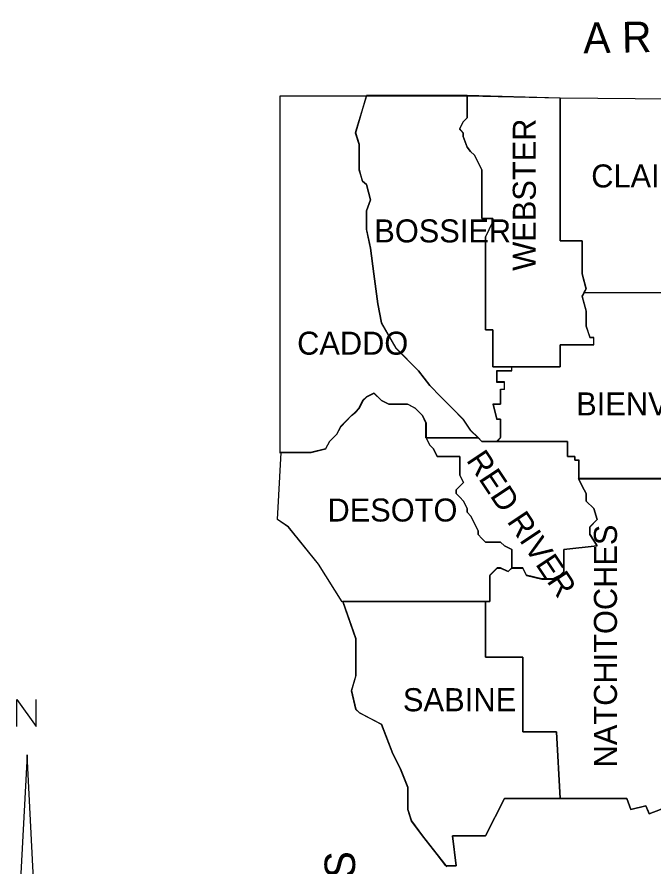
# Model space of a CAD drawing. Extents: x 0.19 to 2.82, y 0.04 to 1.79.
# Drawn here: x 2.1624 to 2.2917, y 1.594 to 1.7666 of the extents above; entities that cross this region are included whole.
import ezdxf

# ---------------------------------------------------------------- set-up
doc = ezdxf.new("R2010")
doc.units = 0
for name, color, linetype in [('Dist04', 7, 'Continuous'), ('Dist08', 7, 'Continuous'), ('Standard Info', 7, 'Continuous')]:
    doc.layers.add(name, color=color, linetype=linetype)

msp = doc.modelspace()

# ---------------------------------------------------------------- linework, layer by layer
at = {"layer": 'Dist04'}
for p, q in [((2.2159, 1.678), (2.2159, 1.75058)), ((2.2159, 1.75058), (2.23332, 1.75058)), ((2.2334, 1.75067), (2.2539, 1.75067)), ((2.2539, 1.75067), (2.27282, 1.75017)), ((2.27282, 1.75017), (2.3099, 1.74983)), ((2.21532, 1.66442), (2.21607, 1.678)), ((2.21607, 1.678), (2.2159, 1.678))]:
    msp.add_line(p, q, dxfattribs=at)
for points in [[(2.27657, 1.67275), (2.27732, 1.67117), (2.27807, 1.66967), (2.27807, 1.66817), (2.27965, 1.66667), (2.28032, 1.66442), (2.27882, 1.66292), (2.27882, 1.66142), (2.28032, 1.65908), (2.27357, 1.65833), (2.27357, 1.65383), (2.27282, 1.65308), (2.27132, 1.65233), (2.26907, 1.65233), (2.26599, 1.65308), (2.26524, 1.65458), (2.26299, 1.65458)], [(2.30307, 1.67275), (2.27665, 1.67275)], [(2.22849, 1.64767), (2.22365, 1.65533), (2.21757, 1.66292), (2.21532, 1.66442)], [(2.26299, 1.65458), (2.26224, 1.65383), (2.26065, 1.65458), (2.25999, 1.65458), (2.25849, 1.65308), (2.25849, 1.64775), (2.25765, 1.64775)], [(2.25765, 1.64775), (2.22865, 1.64775)]]:
    msp.add_lwpolyline(points, dxfattribs=at)
at = {"layer": 'Dist08'}
for points in [[(2.27657, 1.67275), (2.27732, 1.67117), (2.27807, 1.66967), (2.27807, 1.66817), (2.27965, 1.66667), (2.28032, 1.66442), (2.27882, 1.66292), (2.27882, 1.66142), (2.28032, 1.65908), (2.27357, 1.65833), (2.27357, 1.65383), (2.27282, 1.65308), (2.27132, 1.65233), (2.26907, 1.65233), (2.26599, 1.65308), (2.26524, 1.65458), (2.26299, 1.65458)], [(2.30307, 1.67275), (2.27665, 1.67275)], [(2.26299, 1.65458), (2.26224, 1.65383), (2.26065, 1.65458), (2.25999, 1.65458), (2.25849, 1.65308), (2.25849, 1.64775), (2.25765, 1.64775)], [(2.22865, 1.64775), (2.23124, 1.64025), (2.23124, 1.63267), (2.2304, 1.62967), (2.23124, 1.62583), (2.23199, 1.62508), (2.23649, 1.62283), (2.23882, 1.61675), (2.24032, 1.61375), (2.24182, 1.61), (2.24182, 1.60542), (2.24257, 1.60317), (2.24482, 1.60008), (2.24782, 1.59633), (2.24957, 1.59408)], [(2.25765, 1.64775), (2.22865, 1.64775)]]:
    msp.add_lwpolyline(points, dxfattribs=at)
at = {"layer": 'Standard Info'}
for p, q in [((2.2159, 1.67792), (2.2159, 1.75058)), ((2.2159, 1.75058), (2.23332, 1.75058)), ((2.23332, 1.75058), (2.2334, 1.75058)), ((2.2334, 1.75058), (2.2539, 1.75058)), ((2.2539, 1.75058), (2.27282, 1.75017)), ((2.27282, 1.75017), (2.3099, 1.74983)), ((2.27732, 1.70983), (2.27774, 1.71058)), ((2.2629, 1.69542), (2.25915, 1.69542)), ((2.24557, 1.681), (2.25615, 1.681)), ((2.2569, 1.68025), (2.25615, 1.68108)), ((2.2599, 1.68025), (2.2569, 1.68025)), ((2.21532, 1.66442), (2.21607, 1.678)), ((2.22865, 1.64775), (2.22849, 1.64767)), ((2.1644, 1.61657), (2.1624, 1.57857)), ((2.1664, 1.57857), (2.1644, 1.61657)), ((2.2909, 1.60458), (2.29249, 1.60517)), ((2.2499, 1.594), (2.24957, 1.594)), ((2.24965, 1.59383), (2.2499, 1.594))]:
    msp.add_line(p, q, dxfattribs=at)
for points in [[(2.2334, 1.75058), (2.23115, 1.743), (2.2319, 1.74075), (2.2319, 1.73775), (2.2319, 1.7355), (2.23265, 1.73317), (2.2334, 1.7325), (2.23424, 1.72942), (2.2334, 1.72717), (2.2334, 1.72333), (2.23424, 1.71958), (2.2349, 1.71433), (2.23574, 1.70825), (2.23649, 1.70442), (2.23949, 1.69917), (2.24399, 1.69467), (2.24632, 1.69167), (2.24857, 1.68933), (2.25082, 1.68708), (2.25307, 1.68475), (2.25457, 1.6825), (2.25615, 1.681), (2.24549, 1.681), (2.24549, 1.68175), (2.24549, 1.68408), (2.24482, 1.68558), (2.24332, 1.68708), (2.24174, 1.68783), (2.23949, 1.68783), (2.23799, 1.68783), (2.23649, 1.68858), (2.2349, 1.69008), (2.2349, 1.69008), (2.2334, 1.68933), (2.23265, 1.68858), (2.2319, 1.68708), (2.23115, 1.68625), (2.2304, 1.68558), (2.22815, 1.68333), (2.2274, 1.68175), (2.2259, 1.68025), (2.22507, 1.67875), (2.22207, 1.678), (2.21982, 1.678), (2.21607, 1.678)], [(2.25615, 1.68108), (2.25457, 1.68258), (2.25307, 1.68483), (2.25082, 1.68708), (2.24857, 1.68933), (2.24632, 1.69167), (2.24399, 1.69467), (2.23949, 1.69925), (2.23649, 1.70442), (2.23574, 1.70825), (2.2349, 1.71433), (2.23424, 1.71958), (2.2334, 1.72342), (2.2334, 1.72717), (2.23424, 1.72942), (2.2334, 1.7325), (2.23265, 1.73317), (2.23199, 1.7355), (2.23199, 1.73775), (2.23199, 1.74067), (2.23124, 1.743), (2.2334, 1.75058)], [(2.2539, 1.75058), (2.2539, 1.74608), (2.25307, 1.74525), (2.25232, 1.74375), (2.25307, 1.743), (2.25307, 1.74225), (2.2539, 1.74008), (2.25457, 1.73925), (2.2554, 1.7385), (2.25615, 1.73692), (2.2569, 1.7355), (2.2569, 1.73317), (2.2569, 1.73017), (2.2569, 1.72858), (2.2569, 1.72792), (2.2569, 1.72642), (2.2569, 1.72558), (2.25915, 1.72558), (2.25915, 1.72492), (2.25765, 1.72192), (2.25765, 1.703), (2.25915, 1.703), (2.25915, 1.69542), (2.2629, 1.69542), (2.2629, 1.69467), (2.2599, 1.69467), (2.2599, 1.69233), (2.2614, 1.69233), (2.2614, 1.69083), (2.26065, 1.69083), (2.26065, 1.68783), (2.25915, 1.68783), (2.2599, 1.68483), (2.26065, 1.68483), (2.26065, 1.68333), (2.26065, 1.68183), (2.26065, 1.68108), (2.2599, 1.68025)], [(2.25915, 1.69542), (2.25915, 1.703), (2.25765, 1.703), (2.25765, 1.72183), (2.25915, 1.72492), (2.25915, 1.72558), (2.2569, 1.72558), (2.2569, 1.72642), (2.2569, 1.72792), (2.2569, 1.72867), (2.2569, 1.73017), (2.2569, 1.73317), (2.2569, 1.7355), (2.25615, 1.737), (2.2554, 1.7385), (2.25457, 1.73925), (2.2539, 1.74008), (2.25307, 1.74225), (2.25307, 1.743), (2.2524, 1.74383), (2.25307, 1.74525), (2.2539, 1.74608), (2.2539, 1.75058)], [(2.27282, 1.75017), (2.27282, 1.72108), (2.27732, 1.72108), (2.27732, 1.7165), (2.27732, 1.71433), (2.27807, 1.71133), (2.27732, 1.70975), (2.27807, 1.70675), (2.27807, 1.70375), (2.27882, 1.70142), (2.27957, 1.70142), (2.27957, 1.69992), (2.27282, 1.69992), (2.27282, 1.69542), (2.2629, 1.69542)], [(2.27765, 1.7105), (2.27807, 1.71125), (2.27732, 1.71433), (2.27732, 1.7165), (2.27732, 1.72108), (2.27282, 1.72108), (2.27282, 1.75017)], [(2.26299, 1.69542), (2.27282, 1.69542), (2.27282, 1.69992), (2.27965, 1.69992), (2.27965, 1.70142), (2.2789, 1.70142), (2.27807, 1.70375), (2.27807, 1.70683), (2.27732, 1.70983)], [(2.29924, 1.7105), (2.27765, 1.7105)], [(2.27774, 1.71058), (2.29932, 1.71058)], [(2.25999, 1.68025), (2.26065, 1.681), (2.26065, 1.68183), (2.26065, 1.68333), (2.26065, 1.68483), (2.25999, 1.68483), (2.25924, 1.68783), (2.26065, 1.68783), (2.26065, 1.69092), (2.26149, 1.69092), (2.26149, 1.69242), (2.25999, 1.69242), (2.25999, 1.69467), (2.26299, 1.69467), (2.26299, 1.69542)], [(2.21607, 1.678), (2.21982, 1.678), (2.22215, 1.678), (2.22515, 1.67875), (2.2259, 1.68025), (2.2274, 1.68175), (2.22824, 1.68325), (2.2304, 1.68558), (2.23124, 1.68625), (2.23199, 1.68708), (2.23274, 1.68858), (2.23349, 1.68933), (2.23499, 1.69008), (2.23499, 1.69008), (2.23649, 1.68858), (2.23799, 1.68783), (2.23949, 1.68783), (2.24182, 1.68783), (2.24332, 1.68708), (2.24482, 1.68558), (2.24557, 1.68408), (2.24557, 1.68175), (2.24557, 1.681)], [(2.24557, 1.681), (2.24632, 1.6795), (2.24707, 1.67875), (2.24782, 1.67725), (2.2524, 1.67725), (2.2524, 1.67342), (2.25315, 1.67192), (2.2524, 1.67117), (2.25165, 1.67042), (2.25165, 1.66967), (2.2524, 1.66892), (2.25315, 1.66817), (2.2539, 1.66667), (2.2539, 1.66592), (2.25465, 1.66508), (2.2554, 1.66358), (2.25615, 1.66208), (2.25615, 1.66133), (2.2569, 1.66058), (2.25765, 1.65983), (2.25915, 1.65983), (2.26065, 1.65983), (2.26149, 1.65908), (2.26299, 1.65833), (2.26299, 1.6545)], [(2.26299, 1.6545), (2.26299, 1.65833), (2.26149, 1.65908), (2.26065, 1.65983), (2.25915, 1.65983), (2.25765, 1.65983), (2.2569, 1.66058), (2.25615, 1.66133), (2.25615, 1.66208), (2.2554, 1.66358), (2.25465, 1.66508), (2.2539, 1.66592), (2.2539, 1.66667), (2.25315, 1.66817), (2.2524, 1.66892), (2.25165, 1.66967), (2.25165, 1.67042), (2.2524, 1.67117), (2.25315, 1.67192), (2.2524, 1.67342), (2.2524, 1.67725), (2.24782, 1.67725), (2.24707, 1.67875), (2.24632, 1.6795), (2.24557, 1.681)], [(2.25615, 1.681), (2.2569, 1.68025), (2.27432, 1.68025), (2.27432, 1.67725), (2.27582, 1.67725), (2.27582, 1.6765), (2.27657, 1.6765), (2.27657, 1.67267)], [(2.27665, 1.67267), (2.27665, 1.6765), (2.27582, 1.6765), (2.27582, 1.67725), (2.27432, 1.67725), (2.27432, 1.68025), (2.25999, 1.68025)], [(2.25765, 1.64775), (2.25849, 1.64775), (2.25849, 1.653), (2.25999, 1.6545), (2.26065, 1.6545), (2.26224, 1.65383), (2.26299, 1.6545), (2.26524, 1.6545), (2.26599, 1.653), (2.26907, 1.65225), (2.27132, 1.65225), (2.27282, 1.653), (2.27357, 1.65383), (2.27357, 1.65833), (2.28032, 1.65908), (2.27882, 1.66133), (2.27882, 1.66283), (2.28032, 1.66442), (2.27965, 1.66667), (2.27807, 1.66817), (2.27807, 1.66967), (2.27732, 1.67117), (2.27657, 1.67267)], [(2.27657, 1.67267), (2.27732, 1.67117), (2.27807, 1.66967), (2.27807, 1.66817), (2.27965, 1.66667), (2.28032, 1.66442), (2.27882, 1.66283), (2.27882, 1.66133), (2.28032, 1.65908), (2.27357, 1.65833), (2.27357, 1.65383), (2.27282, 1.653), (2.27132, 1.65225), (2.26907, 1.65225), (2.26599, 1.653), (2.26524, 1.6545), (2.26299, 1.6545)], [(2.27657, 1.67267), (2.2944, 1.67267)], [(2.30307, 1.67267), (2.27665, 1.67267)], [(2.22849, 1.64767), (2.22365, 1.65533), (2.21757, 1.66283), (2.21532, 1.66442)], [(2.26299, 1.6545), (2.26224, 1.65383), (2.26065, 1.6545), (2.25999, 1.6545), (2.25849, 1.653), (2.25849, 1.64775), (2.25765, 1.64775)], [(2.25765, 1.64775), (2.22865, 1.64775)], [(2.24957, 1.594), (2.24782, 1.59633), (2.24482, 1.60008), (2.24257, 1.60308), (2.24182, 1.60542), (2.24182, 1.60992), (2.24032, 1.61367), (2.23882, 1.61675), (2.23649, 1.62275), (2.23199, 1.62508), (2.23124, 1.62575), (2.2304, 1.62958), (2.23124, 1.63258), (2.23124, 1.64017), (2.22865, 1.64775)], [(2.22865, 1.64775), (2.25765, 1.64775)], [(2.25765, 1.64775), (2.25765, 1.63642), (2.26524, 1.63642), (2.26524, 1.62125), (2.27207, 1.62125), (2.27282, 1.60767)], [(2.27282, 1.60767), (2.27207, 1.62125), (2.26524, 1.62125), (2.26524, 1.63642), (2.25765, 1.63642), (2.25765, 1.64775)], [(2.16236, 1.62234), (2.16236, 1.62784), (2.16626, 1.62234), (2.16626, 1.62784)], [(2.31057, 1.619), (2.30832, 1.6175), (2.30757, 1.61675), (2.30532, 1.61517), (2.30232, 1.61367), (2.29999, 1.61217), (2.29699, 1.60992), (2.29549, 1.60767), (2.29324, 1.60542), (2.2909, 1.60458)], [(2.2909, 1.60458), (2.29324, 1.60542), (2.29549, 1.60767), (2.29699, 1.60992), (2.29999, 1.61217), (2.30232, 1.61367), (2.30532, 1.61517), (2.30757, 1.61675), (2.30832, 1.6175), (2.31057, 1.619)], [(2.27282, 1.60767), (2.26149, 1.60767), (2.25765, 1.60008), (2.2509, 1.60008), (2.25165, 1.594), (2.2499, 1.594)], [(2.2499, 1.594), (2.25165, 1.594), (2.2509, 1.60008), (2.25765, 1.60008), (2.26149, 1.60767), (2.2864, 1.60767), (2.28715, 1.60542), (2.29024, 1.60617), (2.2909, 1.60458)], [(2.2499, 1.594), (2.25165, 1.594), (2.2509, 1.60008), (2.25765, 1.60008), (2.26149, 1.60767), (2.2864, 1.60767), (2.28715, 1.60542), (2.29024, 1.60617), (2.2909, 1.60467)], [(2.2909, 1.60458), (2.29024, 1.60617), (2.28715, 1.60542), (2.2864, 1.60767), (2.27282, 1.60767)]]:
    msp.add_lwpolyline(points, dxfattribs=at)

# ---------------------------------------------------------------- texts
for s, height, rotation, p in [('A R K A N S A S', 0.0062368, 1.0059, (2.27755, 1.7592)), ('WEBSTER', 0.004679, 90, (2.26786, 1.71498)), ('RED RIVER', 0.004679, 303.6501, (2.2536, 1.67647)), ('NATCHITOCHES', 0.004679, 90, (2.28436, 1.61401)), ('T E X A S', 0.0062, 90, (2.23111, 1.56058))]:
    msp.add_text(s, height=height, rotation=rotation, dxfattribs=at).set_placement(p)
for s, height, p in [('CLAIBORNE', 0.004679, (2.27913, 1.73192)), ('BOSSIER', 0.004679, (2.23502, 1.72075)), ('CADDO', 0.004679, (2.21933, 1.69792)), ('BIENVILLE', 0.004679, (2.27608, 1.68558)), ('DESOTO', 0.004679, (2.2255, 1.664)), ('SABINE', 0.0047, (2.24083, 1.62542))]:
    msp.add_text(s, height=height, dxfattribs=at).set_placement(p)

doc.saveas('drawing.dxf')
